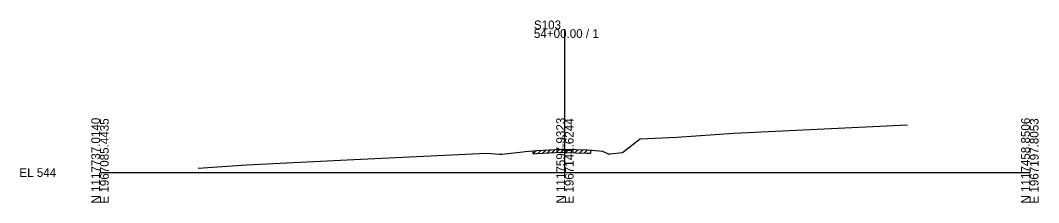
# Model space of a CAD drawing. Extents: x 974 to 1303, y 990 to 14518.
# Drawn here: x 974.3 to 1302.8, y 2990.3 to 3049.1 of the extents above; entities that cross this region are included whole.
import ezdxf

# ---------------------------------------------------------------- set-up
doc = ezdxf.new("R2010")
doc.units = 0
for name, color, linetype in [('Level 10', 7, 'Continuous'), ('Level 60', 7, 'Continuous'), ('Level 61', 7, 'Continuous'), ('Level 63', 7, 'Continuous')]:
    doc.layers.add(name, color=color, linetype=linetype)

msp = doc.modelspace()

# ---------------------------------------------------------------- linework, layer by layer
at = {"layer": 'Level 60'}
for p, q in [((1186.09, 3011.38), (1204.54, 3012.72)), ((1204.54, 3012.72), (1260.52, 3015.41)), ((1168.54, 3006.48), (1173.97, 3010.63)), ((1173.97, 3010.63), (1174.3, 3010.9)), ((1174.3, 3010.9), (1186.09, 3011.38)), ((1108.94, 3005.53), (1124.67, 3006.27)), ((1124.67, 3006.27), (1128.93, 3005.94)), ((1129.62, 3005.88), (1136.38, 3006.64)), ((1136.38, 3006.64), (1137.22, 3006.74)), ((1137.22, 3006.74), (1139.81, 3007.03)), ((1139.81, 3007.03), (1140.9, 3007.1)), ((1140.9, 3007.1), (1148.85, 3007.56)), ((1148.85, 3007.56), (1150, 3007.52)), ((1150, 3007.52), (1157.05, 3007.3)), ((1157.05, 3007.3), (1158.23, 3007.27)), ((1158.23, 3007.27), (1158.75, 3007.21)), ((1158.75, 3007.21), (1162.1, 3006.85)), ((1162.1, 3006.85), (1163.93, 3006.03)), ((1163.93, 3006.03), (1164.62, 3006.08)), ((1164.62, 3006.08), (1168.54, 3006.48)), ((1047.4, 3002.45), (1081.85, 3004.23)), ((1081.85, 3004.23), (1108.94, 3005.53)), ((1128.93, 3005.94), (1129.62, 3005.88)), ((1031.64, 3001.42), (1047.4, 3002.45))]:
    msp.add_line(p, q, dxfattribs=at)
at = {"layer": 'Level 61'}
for p, q in [((1139.81, 3006.03), (1140.88, 3007.1)), ((1139.81, 3006.03), (1139.81, 3007.03)), ((1139.81, 3006.03), (1140.9, 3006.1)), ((1140.9, 3006.1), (1148.85, 3006.56)), ((1141.31, 3006.12), (1142.37, 3007.19)), ((1142.81, 3006.21), (1143.87, 3007.27)), ((1144.31, 3006.3), (1145.37, 3007.36)), ((1145.81, 3006.38), (1146.87, 3007.44)), ((1147.31, 3006.47), (1148.37, 3007.53)), ((1148.81, 3006.56), (1149.79, 3007.53)), ((1148.85, 3006.56), (1150, 3006.52)), ((1150, 3006.52), (1157.05, 3006.3)), ((1150.31, 3006.51), (1151.28, 3007.48)), ((1151.81, 3006.46), (1152.78, 3007.43)), ((1153.31, 3006.42), (1154.28, 3007.39)), ((1154.81, 3006.37), (1155.78, 3007.34)), ((1156.31, 3006.32), (1157.28, 3007.29)), ((1157.05, 3006.3), (1158.23, 3006.27)), ((1158.23, 3007.27), (1158.23, 3006.27)), ((1139.81, 3006.03), (1139.81, 3006.03))]:
    msp.add_line(p, q, dxfattribs=at)
at = {"layer": 'Level 63'}
for p, q in [((1150, 3000), (1150, 3046.23)), ((1000, 3000), (1150, 3000)), ((1150, 3000), (1300, 3000))]:
    msp.add_line(p, q, dxfattribs=at)

# ---------------------------------------------------------------- texts
at = {"layer": 'Level 10'}
msp.add_text('551.52', height=0.9, rotation=90, dxfattribs=at).set_placement((1149.95, 3008.02))
at = {"layer": 'Level 63'}
for s, p in [('S103', (1140, 3046.23)), ('54+00.00 / 1', (1140, 3043.43)), ('EL 544', (974, 2998.6))]:
    msp.add_text(s, height=2.8, dxfattribs=at).set_placement(p)
for s, p in [('N 1117737.0140', (1000, 2990)), ('E 1967085.4435', (1002.8, 2990)), ('N 1117597.9323', (1150, 2990)), ('E 1967141.6244', (1152.8, 2990)), ('N 1117458.8506', (1300, 2990)), ('E 1967197.8053', (1302.8, 2990))]:
    msp.add_text(s, height=2.8, rotation=90, dxfattribs=at).set_placement(p)

doc.saveas('drawing.dxf')
